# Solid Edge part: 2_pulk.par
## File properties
Author: Romil
Template: iso part.par
Last saved by: Romil
Revision: 35
Application: Solid Edge
Accuracy: 0.990
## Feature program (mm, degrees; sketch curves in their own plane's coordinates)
sketch for "unnamed Protrusion 1" plane through (0, 0, 0) normal (1, 0, 0) x-axis (0, 1, 0)
  arc centre (0, 0) radius 2.35 from (2.181, 0.875) to (2.181, -0.875) cw
  arc centre (0, 0) radius 2.35 from (-0.875, 2.181) to (0.875, 2.181) cw
  arc centre (0, 0) radius 2.35 from (-2.181, -0.875) to (-2.181, 0.875) cw
extrude "unnamed Protrusion 1" add finite 15.2 symmetric
fillet "Round_4" radius 0.55  Radii2 = 0.2 mm
mirror "unnamed Mirror 1" of "Round_4" about plane through (0, 0, 0) normal (1, 0, 0)
fillet "unnamed Round 1"
sketch for "unnamed Cutout 1" plane through (0, 0, 0) normal (0, -1, 0) x-axis (1, 0, 0)
extrude "unnamed Cutout 1" cut finite 17.6077 symmetric
sketch for "unnamed Cutout 2" plane through (0, 0, 0) normal (0, 0, 1) x-axis (1, 0, 0)
extrude "unnamed Cutout 2" cut finite 17.5826 symmetric
mirror "unnamed Mirror 2" of "unnamed Cutout 1" about plane through (0, 0, 0) normal (0, 0, 1)
extrude "unnamed Cutout 3" cut finite 17.6077 symmetric
mirror "unnamed Mirror 3" of "unnamed Cutout 2" about plane through (0, 0, 0) normal (0, -1, 0)
extrude "unnamed Cutout 4" cut finite 17.5826 symmetric
mirror "unnamed Mirror 4" of "unnamed Cutout 1", "unnamed Mirror 2", "unnamed Mirror 3", "unnamed Cutout 2" about plane through (0, 0, 0) normal (1, 0, 0)
extrude "unnamed Cutout 5" cut finite 17.6077 symmetric
extrude "unnamed Cutout 6" cut finite 17.5826 symmetric
extrude "unnamed Cutout 7" cut finite 17.6077 symmetric
extrude "unnamed Cutout 8" cut finite 17.5826 symmetric
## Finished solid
Body 1: solid body, 82 faces, 224 edges, 144 vertices.
  Faces by surface: plane 34, cylinder 32, torus 16
  Edges by curve: line 128, circle 64, intersection 32
Bounding box of the edges (mm; curved faces can reach further): 15.200 x 4.700 x 4.700, from (-7.6, -2.35, -2.35) to (7.6, 2.35, 2.35).
Cylindrical faces by radius (mm): R0.1 x4, R0.2 x16, R2.35 x12
Toroidal faces (ring radius, tube radius in mm): R0.3 r0.2 x8, R1.8 r0.55 x8
Planar faces by outward normal: +x 9, +y 4, +z 4, -x 9, -y 4, -z 4
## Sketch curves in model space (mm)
line (-5.2451, 0, 1.3) -> (-4.0461, 0, 1.3)
line (-4.0461, 0, 1.3) -> (-4.0461, 0, 3.3)
line (-5.2451, 0, 3.3) -> (-4.0461, 0, 3.3)
line (-5.2451, 0, 3.3) -> (-5.2451, 0, 1.3)
line (-4.05, 1.3, 0) -> (-4.05, 3.3, 0)
line (-4.05, 3.3, 0) -> (-5.25, 3.3, 0)
line (-5.25, 3.3, 0) -> (-5.25, 1.3, 0)
line (-5.25, 1.3, 0) -> (-4.05, 1.3, 0)
arc centre (0, -0.975, -0.975) radius 0.1 from (0, -0.975, -0.875) through (0, -0.9023, -0.9064) to (0, -0.875, -0.975)
line (0, -0.875, -0.975) -> (0, -0.875, -2.181)
arc centre (0, 0, 0) radius 2.35 from (0, 0.875, -2.181) through (0, 0, -2.35) to (0, -0.875, -2.181)
line (0, 0.875, -2.181) -> (0, 0.875, -0.975)
arc centre (0, 0.975, -0.975) radius 0.1 from (0, 0.875, -0.975) through (0, 0.9064, -0.9023) to (0, 0.975, -0.875)
line (0, 0.975, -0.875) -> (0, 2.181, -0.875)
arc centre (0, 0, 0) radius 2.35 from (0, 2.181, 0.875) through (0, 2.35, 0) to (0, 2.181, -0.875)
line (0, 2.181, 0.875) -> (0, 0.975, 0.875)
arc centre (0, 0.975, 0.975) radius 0.1 from (0, 0.975, 0.875) through (0, 0.9023, 0.9064) to (0, 0.875, 0.975)
line (0, 0.875, 0.975) -> (0, 0.875, 2.181)
arc centre (0, 0, 0) radius 2.35 from (0, -0.875, 2.181) through (0, 0, 2.35) to (0, 0.875, 2.181)
line (0, -0.875, 2.181) -> (0, -0.875, 0.975)
arc centre (0, -0.975, 0.975) radius 0.1 from (0, -0.875, 0.975) through (0, -0.9064, 0.9023) to (0, -0.975, 0.875)
line (0, -0.975, 0.875) -> (0, -2.181, 0.875)
arc centre (0, 0, 0) radius 2.35 from (0, -2.181, -0.875) through (0, -2.35, 0) to (0, -2.181, 0.875)
line (0, -2.181, -0.875) -> (0, -0.975, -0.875)
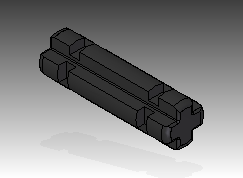
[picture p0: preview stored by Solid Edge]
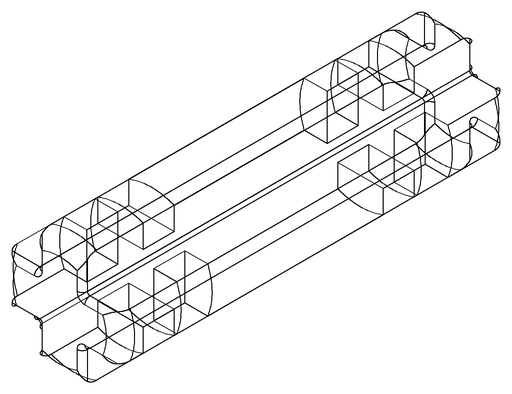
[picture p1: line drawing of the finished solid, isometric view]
